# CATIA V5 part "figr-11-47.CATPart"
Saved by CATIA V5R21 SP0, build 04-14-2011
Part number: Part1
Bounding box of the stored display mesh (mm): x -171.181 to 0, y -220 to 0, z -11.432 to 46.691
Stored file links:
  D:\CATIA V5R21 E-RESOURCES\CATIA-V5R21\catia-v5r21-prt\c11-catia-v5r21-prt\c11-catia-v5r21-figr-11-47.CATPart
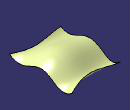
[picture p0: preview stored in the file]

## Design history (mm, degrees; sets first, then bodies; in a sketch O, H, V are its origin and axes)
Set1
  Sweep1: type Unspec, Profile Sketch2, Guide Sketch1
Body1 (main body)
  Sketch1 on yz-plane, origin (0, 0, 0), H (0, 1, 0), V (0, 0, 1)
    spline S1 through (0, 0) (-40, -10) (-100, 20) (-170, 0) (-220, 10)
    point P1 (0, 0)
    coincidence: P1 O
  Sketch2 on zx-plane, origin (0, 0, 0), H (-1, 0, 0), V (0, 0, 1)
    spline S1 through (0, 0) (60, 30) (121.1814, 19.9844) (171.1814, 9.9844)
    point P1 (0, 0)
    coincidence: P1 O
